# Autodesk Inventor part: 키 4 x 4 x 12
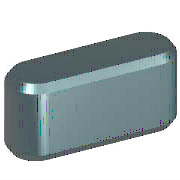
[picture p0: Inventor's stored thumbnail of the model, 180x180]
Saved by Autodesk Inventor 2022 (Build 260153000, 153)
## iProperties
IsCustomPart: 1
Created: 2012-02
Part Number: 키 4 x 4 x 12
Material: 강철, 연강
Description: 키 및 해당 키홈
Document SubType Name: Modeling
Standard: KS B 1311
Designer: mduedu
Standards Organization: KS
Language: ko-KR
Size Designation: 4 x 4 x 12
Categories: <MemberInstance><Categories><Category DisplayName="샤프트 부품" InternalName="7f7aeb1f-a693-4053-b835-cee3144e0d98" Mnemonic="SHFT"><Category DisplayName="키" Interna
Density: 1 g/cm^3
Appearance: 노란색
Author: mduedu
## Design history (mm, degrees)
workplane "Work Plane1"
workplane "Work Plane2"
sketch "스케치1"
  geometry: L1 (2, 2)-(10, 2); L2 (10, -2)-(2, -2); L3 (0, 9.4)-(0, -7.4) reference; L4 (-5, 0)-(30, 0) reference; L5 (12, 0)-(12, 7); A1 r 2 centre (2, 0) between (2, 2) and (2, -2); A2 r 2 centre (10, 0) between (10, -2) and (10, 2)
  constraints: 6 end point, 5 point on circle, 4 tangent, 3 point on line, 2 centre point, 1 horizontal, 1 parallel, 1 perpendicular
  dimensions: "d0" = 2 radius of A1 (= 0.5 x PB); "d13" = 2 radius of A2 (= 0.5 x PB); "d14" = 12 distance between parallel lines of L5 L3 (= NLG)
extrude "본체1" new body sketch "스케치1" taper "d3" = 0 deg; stored distance "d4" = 10
workplane "Work Plane3"
body "Solid1"
chamfer "모따기1" distance "d8" = 0.25 (= PHH); stored, may be unused: second distance "d9" = 0.25 (= PHH), angle "d15" = 45 deg
other parameters: "d1" = -2.5 (= -PNT), "d2" = 1.5 (= PH - PNT), "NLG" = 12 [user parameter; used in 3 equation terms], "PB" = 4 [user parameter; used in 2 equation terms], "PNT" = 2.5 [user parameter; used in 2 equation terms], "PH" = 4 [user parameter; used in 1 equation term], "PHH" = 0.25 [user parameter; used in 2 equation terms], "d10" = 0, "d16" = 0, "d17" = 0, "d18" = 0, "PLB2" = 12 (= NLG) [user parameter], "WDMAX" = 12 [user parameter], "PLB1" = 12 (= NLG) [user parameter], "RR" = 0.08 [user parameter], "PUEB" = 1.8 [user parameter]
